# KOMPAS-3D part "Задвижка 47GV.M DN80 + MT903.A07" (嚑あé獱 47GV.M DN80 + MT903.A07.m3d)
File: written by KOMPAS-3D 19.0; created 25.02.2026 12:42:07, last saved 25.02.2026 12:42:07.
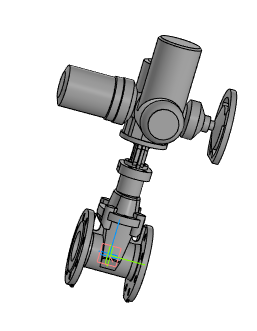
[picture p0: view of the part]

Document properties: Автор: Энергия; Полное имя файла: 47GV.M DN80\Задвижка 47GV.M DN80 с переходом под ISO фланец.a3d

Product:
- Part/product: Задвижка 47GV.M DN80 + MT903.A07
    Масса: 87.5652
  - Component: Задвижка с обрезиненным клином DN80. Сборочный чертеж  | designation DR.47GVM.080.16.00.00СБ  | pos. 0  | Масса: 15.8764; Раздел спецификации: Документация; Форматы листов документа: 2xA3; source file: 47GV.M DN80\DR.47GVM.080.16.00.000 СБ - Задвижка с обрезиненным клином DN80.cdw
- Part/product: Задвижка 47GV.M DN80 + MT903.A07  | designation 01
    Масса: 15.8677
  - Component [detail]: Стойка  | Материал: ВЧ50 ГОСТ 7293-85 (density 7200 kg/m3); Масса: 1.9123; source file: 47GV.M DN80\DR.47GVAM.100.16.00.001 - Стойка.cdw, 47GV.M DN80\Стойка DN100.m3d
  - Component [detail]: Удлинитель шпинделя  | Материал: Сталь 20Х13 ГОСТ 5632-72 (density 7670 kg/m3); Масса: 0.393756; source file: 47GV.M DN80\DR.47GVAM.100.16.00.002 - Удлинитель шпинделя.cdw, 47GV.M DN80\Удлинитель шпинделя DN100.m3d
  - Component [detail]: Крышка DN80  | pos. 4  | Материал: ВЧ50 ГОСТ 7293-85 (density 7200 kg/m3); Масса: 5.8711; Раздел спецификации: Детали; Форматы листов документа: 2xA3; source file: 47GV.M DN80\DR.47GVM.080.16.00.002 - Крышка.cdw, 47GV.M DN80\Крышка DN80.m3d
  - Component [detail]: Корпус DN80  | pos. 3  | Материал: ВЧ50 ГОСТ 7293-85 (density 7200 kg/m3); Масса: 13.7997; Раздел спецификации: Детали; Форматы листов документа: 2xA3; source file: 47GV.M DN80\DR.47GVM.050.16.00.001 - Корпус.cdw, 47GV.M DN80\DR.47GVM.080.16.00.001 - Корпус.cdw, 47GV.M DN80\Корпус DN80.m3d
  - Component [assembly]: Клин с направляющими  | designation DR.47GVM.080.16.01.000  | pos. 4  | Раздел спецификации: Сборочные единицы; Форматы листов документа: A4; source file: 47GV.M DN80\DR.47GVM.080.16.01.000 - Клин с направляющими.a3d, 47GV.M DN80\DR.47GVM.080.16.01.000 - Клин с направляющими.spw, 47GV.M DN80\DR.47GVM.080.16.01.000 СБ - Клин с направляющими.cdw
  - Component [detail]: Шпиндель  | pos. 5  | Материал: Сталь 20Х13 ГОСТ 5632 - 2014 (density 7670 kg/m3); Масса: 0.114456; Раздел спецификации: Детали; Форматы листов документа: A3; source file: 47GV.M DN80\DR.47GVM.080.16.00.003 - Шпиндель.cdw, 47GV.M DN80\Шпиндель DN80.m3d
  - Component: Электропривод МТ903.А07 без блока управления  | Масса: 65.4738; source file: 47GV.M DN50\Электропривод МТ903.А07 без блока управления.m3d

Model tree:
1. Операция без истории:1

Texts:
  Точка начала. Х
  Точка начала. Y
  Точка начала. Z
